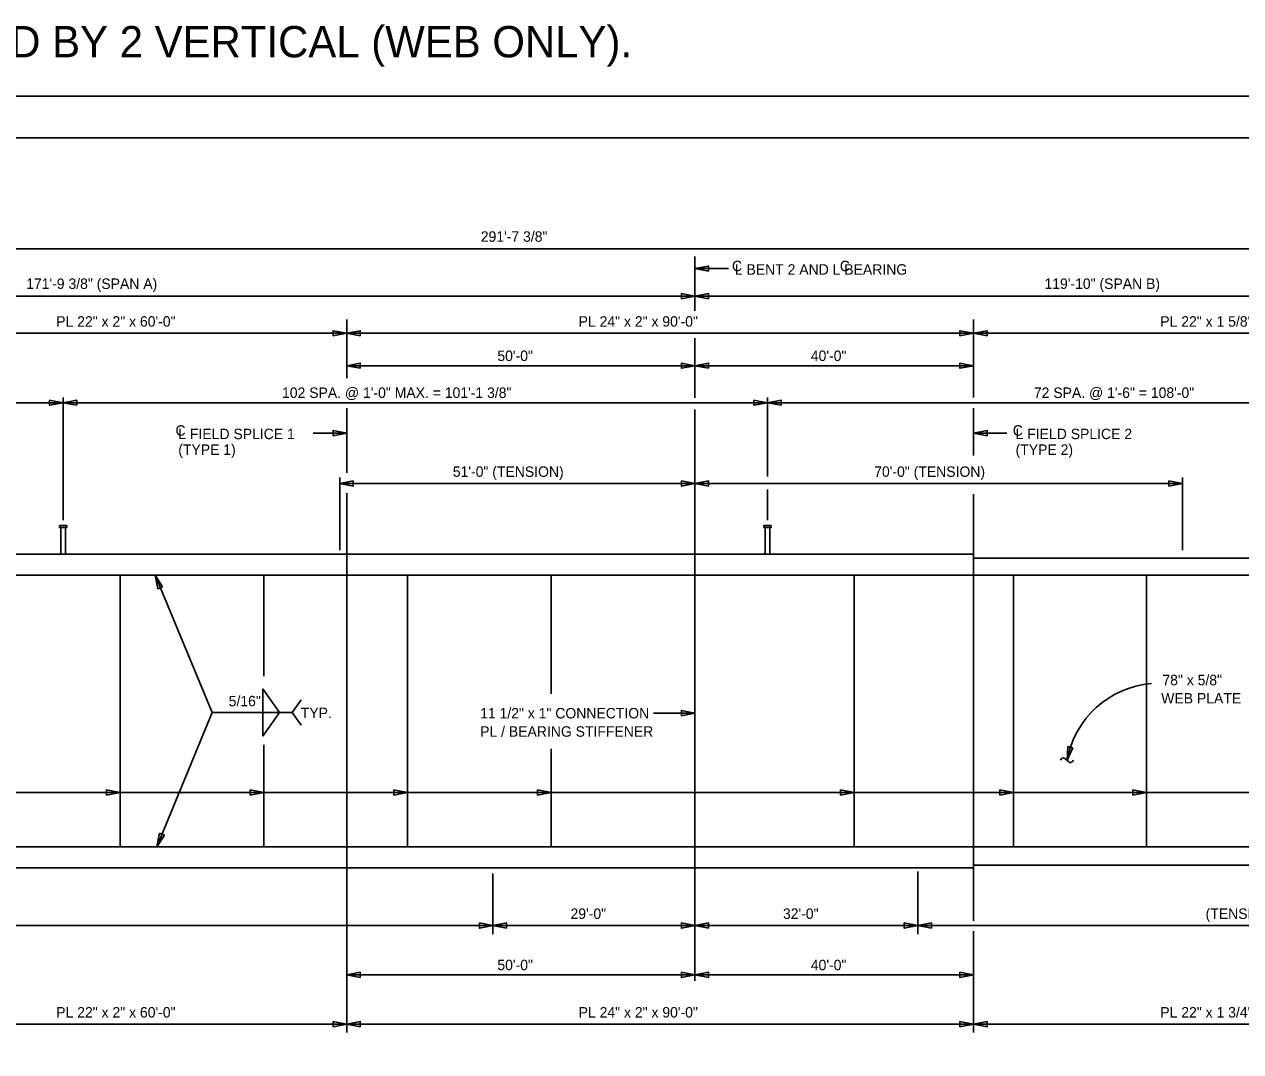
# Model space of a CAD drawing. Extents: x -383 to 3, y -322 to -94.
# Drawn here: x -253.2 to -195, y -145.2 to -96.1 of the extents above; entities that cross this region are included whole.
import ezdxf

# ---------------------------------------------------------------- set-up
doc = ezdxf.new("R2010")
doc.units = 0
for name, color, linetype in [('BR_AUTO DIMENSION', 7, 'Continuous'), ('BR_BORDER LINES', 7, 'Continuous'), ('BR_CENTER LINES', 7, 'Continuous'), ('BR_STRUCTURAL STEEL', 7, 'Continuous'), ('BR_TEXT', 7, 'Continuous'), ('Default', 7, 'Continuous'), ('Level 31', 7, 'Continuous')]:
    doc.layers.add(name, color=color, linetype=linetype)

msp = doc.modelspace()

# ---------------------------------------------------------------- linework, layer by layer
at = {"layer": 'BR_AUTO DIMENSION'}
for p, q in [((-278.395, -106.806), (-181.19, -106.806)), ((-221.135, -107.745), (-219.537, -107.745)), ((-278.395, -109.064), (-221.135, -109.064)), ((-221.135, -109.064), (-181.19, -109.064)), ((-257.802, -110.841), (-237.802, -110.841)), ((-237.802, -110.841), (-207.802, -110.841)), ((-207.802, -110.841), (-181.19, -110.841)), ((-221.135, -112.391), (-237.802, -112.391)), ((-207.802, -112.391), (-221.135, -112.391)), ((-251.367, -119.779), (-251.367, -113.909)), ((-217.663, -117.684), (-217.663, -113.909)), ((-276.728, -114.159), (-251.367, -114.159)), ((-251.367, -114.159), (-217.663, -114.159)), ((-217.663, -114.159), (-182.385, -114.159)), ((-237.802, -115.615), (-239.401, -115.615)), ((-207.802, -115.615), (-206.203, -115.615)), ((-238.135, -117.738), (-238.135, -121.213)), ((-238.135, -118.028), (-221.135, -118.028)), ((-197.802, -118.028), (-221.135, -118.028)), ((-197.802, -117.738), (-197.802, -121.213)), ((-217.663, -119.787), (-217.663, -118.317)), ((-244.237, -128.987), (-246.974, -122.412)), ((-241.821, -127.854), (-241.821, -130.121)), ((-241.821, -127.854), (-241.016, -128.987)), ((-240.412, -128.987), (-239.98, -128.38)), ((-244.237, -128.987), (-246.886, -135.412)), ((-244.237, -128.987), (-240.412, -128.987)), ((-241.821, -130.121), (-241.016, -128.987)), ((-240.412, -128.987), (-239.98, -129.595)), ((-221.135, -129.011), (-223.126, -129.011)), ((-186.804, -132.816), (-283.86, -132.816)), ((-230.802, -136.687), (-230.802, -139.586)), ((-210.469, -136.592), (-210.469, -139.586)), ((-230.802, -139.18), (-278.395, -139.18)), ((-221.135, -139.18), (-230.802, -139.18)), ((-210.469, -139.18), (-221.135, -139.18)), ((-181.19, -139.18), (-210.469, -139.18)), ((-221.135, -141.539), (-237.802, -141.539)), ((-207.802, -141.539), (-221.135, -141.539)), ((-257.802, -143.898), (-237.802, -143.898)), ((-237.802, -143.898), (-207.802, -143.898)), ((-207.802, -143.898), (-181.19, -143.898))]:
    msp.add_line(p, q, dxfattribs=at)
for points in [[(-220.485, -107.87), (-221.135, -107.745), (-220.485, -107.62)], [(-221.785, -109.189), (-221.135, -109.064), (-221.785, -108.939)], [(-220.485, -109.189), (-221.135, -109.064), (-220.485, -108.939)], [(-238.452, -110.966), (-237.802, -110.841), (-238.452, -110.716)], [(-237.152, -110.966), (-237.802, -110.841), (-237.152, -110.716)], [(-208.452, -110.966), (-207.802, -110.841), (-208.452, -110.716)], [(-207.152, -110.966), (-207.802, -110.841), (-207.152, -110.716)], [(-237.152, -112.516), (-237.802, -112.391), (-237.152, -112.266)], [(-221.785, -112.266), (-221.135, -112.391), (-221.785, -112.516)], [(-220.485, -112.516), (-221.135, -112.391), (-220.485, -112.266)], [(-208.452, -112.266), (-207.802, -112.391), (-208.452, -112.516)], [(-252.017, -114.034), (-251.367, -114.159), (-252.017, -114.284)], [(-250.717, -114.284), (-251.367, -114.159), (-250.717, -114.034)], [(-218.313, -114.034), (-217.663, -114.159), (-218.313, -114.284)], [(-217.013, -114.284), (-217.663, -114.159), (-217.013, -114.034)], [(-238.452, -115.74), (-237.802, -115.615), (-238.452, -115.49)], [(-207.152, -115.74), (-207.802, -115.615), (-207.152, -115.49)], [(-237.485, -117.903), (-238.135, -118.028), (-237.485, -118.153)], [(-221.785, -117.903), (-221.135, -118.028), (-221.785, -118.153)], [(-220.485, -118.153), (-221.135, -118.028), (-220.485, -117.903)], [(-198.452, -117.903), (-197.802, -118.028), (-198.452, -118.153)], [(-246.609, -122.964), (-246.974, -122.412), (-246.84, -123.061)], [(-221.785, -129.136), (-221.135, -129.011), (-221.785, -128.886)], [(-203.047, -130.673), (-203.33, -131.271), (-203.289, -130.611)], [(-249.297, -132.941), (-248.647, -132.816), (-249.297, -132.691)], [(-242.419, -132.941), (-241.769, -132.816), (-242.419, -132.691)], [(-235.541, -132.941), (-234.891, -132.816), (-235.541, -132.691)], [(-228.663, -132.941), (-228.013, -132.816), (-228.663, -132.691)], [(-214.163, -132.941), (-213.513, -132.816), (-214.163, -132.691)], [(-206.54, -132.941), (-205.89, -132.816), (-206.54, -132.691)], [(-200.178, -132.941), (-199.528, -132.816), (-200.178, -132.691)], [(-246.754, -134.764), (-246.886, -135.412), (-246.523, -134.859)], [(-231.452, -139.055), (-230.802, -139.18), (-231.452, -139.305)], [(-230.152, -139.305), (-230.802, -139.18), (-230.152, -139.055)], [(-221.785, -139.055), (-221.135, -139.18), (-221.785, -139.305)], [(-220.485, -139.305), (-221.135, -139.18), (-220.485, -139.055)], [(-211.119, -139.055), (-210.469, -139.18), (-211.119, -139.305)], [(-209.819, -139.305), (-210.469, -139.18), (-209.819, -139.055)], [(-237.152, -141.664), (-237.802, -141.539), (-237.152, -141.414)], [(-221.785, -141.414), (-221.135, -141.539), (-221.785, -141.664)], [(-220.485, -141.664), (-221.135, -141.539), (-220.485, -141.414)], [(-208.452, -141.414), (-207.802, -141.539), (-208.452, -141.664)], [(-238.452, -143.773), (-237.802, -143.898), (-238.452, -144.023)], [(-237.152, -144.023), (-237.802, -143.898), (-237.152, -143.773)], [(-208.452, -143.773), (-207.802, -143.898), (-208.452, -144.023)], [(-207.152, -144.023), (-207.802, -143.898), (-207.152, -143.773)]]:
    msp.add_lwpolyline(points, close=True, dxfattribs=at)
msp.add_arc((-198.905, -132.075), 4.497, 94.96239, 169.7037, dxfattribs=at)
at = {"layer": 'BR_BORDER LINES'}
msp.add_line((-163.178, -101.489), (-297.843, -101.489), dxfattribs=at)
at = {"layer": 'BR_CENTER LINES'}
for p, q in [((-221.135, -107.17), (-221.135, -109.769)), ((-237.802, -110.184), (-237.802, -112.985)), ((-207.802, -110.184), (-207.802, -113.912)), ((-221.135, -111.078), (-221.135, -113.935)), ((-237.802, -114.42), (-237.802, -117.523)), ((-221.135, -114.486), (-221.135, -122.412)), ((-207.802, -114.419), (-207.802, -116.684)), ((-237.802, -118.493), (-237.802, -144.298)), ((-207.802, -118.539), (-207.802, -138.953)), ((-221.135, -135.412), (-221.135, -141.826)), ((-207.802, -139.444), (-207.802, -144.298))]:
    msp.add_line(p, q, dxfattribs=at)
at = {"layer": 'BR_STRUCTURAL STEEL'}
for p, q in [((-257.802, -121.412), (-237.802, -121.412)), ((-237.802, -121.412), (-237.802, -122.412)), ((-237.802, -121.412), (-207.802, -121.412)), ((-207.802, -121.412), (-207.802, -122.412)), ((-207.802, -121.6), (-181.19, -121.6)), ((-278.395, -122.412), (-181.19, -122.412)), ((-248.647, -122.412), (-248.647, -135.412)), ((-241.769, -122.412), (-241.769, -127.24)), ((-234.891, -122.412), (-234.891, -135.412)), ((-228.013, -122.412), (-228.013, -128.083)), ((-221.135, -122.412), (-221.135, -135.412)), ((-213.513, -122.412), (-213.513, -135.412)), ((-205.89, -122.412), (-205.89, -135.412)), ((-199.528, -122.412), (-199.528, -135.412)), ((-241.769, -130.537), (-241.769, -135.412)), ((-228.013, -130.716), (-228.013, -135.412)), ((-278.395, -135.412), (-181.19, -135.412)), ((-237.802, -135.412), (-237.802, -136.412)), ((-237.802, -135.412), (-237.802, -136.412)), ((-207.802, -135.412), (-207.802, -136.412)), ((-257.802, -136.412), (-237.802, -136.412)), ((-237.802, -136.412), (-207.802, -136.412)), ((-207.802, -136.287), (-181.19, -136.287))]:
    msp.add_line(p, q, dxfattribs=at)
at = {"layer": 'BR_TEXT'}
for p, q in [((-203.644, -131.263), (-203.615, -131.217)), ((-203.411, -131.197), (-203.248, -131.346)), ((-203.07, -131.324), (-203.027, -131.263))]:
    msp.add_line(p, q, dxfattribs=at)
for centre, radius, start, end in [((-203.505, -131.278), 0.125, 41.00704, 150.80591), ((-203.167, -131.271), 0.111, 223.45189, 331.73747)]:
    msp.add_arc(centre, radius, start, end, dxfattribs=at)
at = {"layer": 'Default'}
for p, q in [((-251.539, -120.037), (-251.539, -120.131)), ((-251.539, -120.037), (-251.195, -120.037)), ((-251.539, -120.131), (-251.195, -120.131)), ((-251.477, -120.131), (-251.477, -121.412)), ((-251.258, -120.131), (-251.258, -121.412)), ((-251.195, -120.037), (-251.195, -120.131)), ((-217.835, -120.037), (-217.835, -120.131)), ((-217.835, -120.037), (-217.491, -120.037)), ((-217.835, -120.131), (-217.491, -120.131)), ((-217.772, -120.131), (-217.772, -121.412)), ((-217.553, -120.131), (-217.553, -121.412)), ((-217.491, -120.037), (-217.491, -120.131))]:
    msp.add_line(p, q, dxfattribs=at)
at = {"layer": 'Level 31'}
msp.add_lwpolyline([(-305.176, -187.489), (-161.176, -187.489), (-161.176, -99.489), (-305.176, -99.489)], close=True, dxfattribs=at)

# ---------------------------------------------------------------- texts
at = {"layer": 'BR_AUTO DIMENSION'}
for s, p in [('291\'-7 3/8"', (-231.384, -106.46)), ('171\'-9 3/8" (SPAN A)', (-253.14, -108.717)), ('119\'-10" (SPAN B)', (-204.409, -108.717)), ('PL 22" x 2" x 60\'-0"', (-251.701, -110.522)), ('PL 24" x 2" x 90\'-0"', (-226.701, -110.522)), ('PL 22" x 1 5/8" x 79\'-10"', (-198.865, -110.522)), ('50\'-0"', (-230.59, -112.166)), ('40\'-0"', (-215.59, -112.166)), ('102 SPA. @ 1\'-0" MAX. = 101\'-1 3/8"', (-240.896, -113.933)), ('72 SPA. @ 1\'-6" = 108\'-0"', (-204.915, -113.933)), (' 70\'-0" (TENSION)', (-212.743, -117.708)), ('78" x 5/8" ', (-198.764, -127.678)), ('WEB PLATE', (-198.822, -128.553)), ('5/16"', (-243.449, -128.687)), ('TYP.', (-239.996, -129.254)), ('29\'-0"', (-227.09, -138.86)), ('(TENSION)', (-196.697, -138.86)), ('50\'-0"', (-230.59, -141.314)), ('40\'-0"', (-215.59, -141.314)), ('PL 22" x 2" x 60\'-0"', (-251.701, -143.579)), ('PL 24" x 2" x 90\'-0"', (-226.701, -143.579)), ('PL 22" x 1 3/4" x 79\'-10"', (-198.865, -143.579))]:
    msp.add_text(s, height=0.5, rotation=360, dxfattribs=at).set_placement(p)
for s, p in [(' 51\'-0" (TENSION)', (-232.909, -117.708)), ('32\'-0"', (-216.923, -138.86))]:
    msp.add_text(s, height=0.5, dxfattribs=at).set_placement(p)
at = {"layer": 'BR_TEXT'}
msp.add_text('EXAGGERATED BY 6 VERTICAL (FLANGES ONLY) AND BY 2 VERTICAL (WEB ONLY).', height=1.5, dxfattribs=at).set_placement((-305.065, -97.636))
for s, p in [('C', (-219.363, -107.869)), ('L BENT 2 AND L BEARING', (-219.227, -108.035)), ('C', (-214.203, -107.869)), ('C', (-245.995, -115.739)), ('C', (-205.925, -115.739)), ('L FIELD SPLICE 1', (-245.86, -115.905)), ('L FIELD SPLICE 2', (-205.79, -115.905)), ('(TYPE 1)', (-245.86, -116.655)), ('(TYPE 2)', (-205.79, -116.655)), ('11 1/2" x 1" CONNECTION ', (-231.415, -129.268)), ('PL / BEARING STIFFENER', (-231.415, -130.143))]:
    msp.add_text(s, height=0.5, rotation=360, dxfattribs=at).set_placement(p)

doc.saveas('drawing.dxf')
